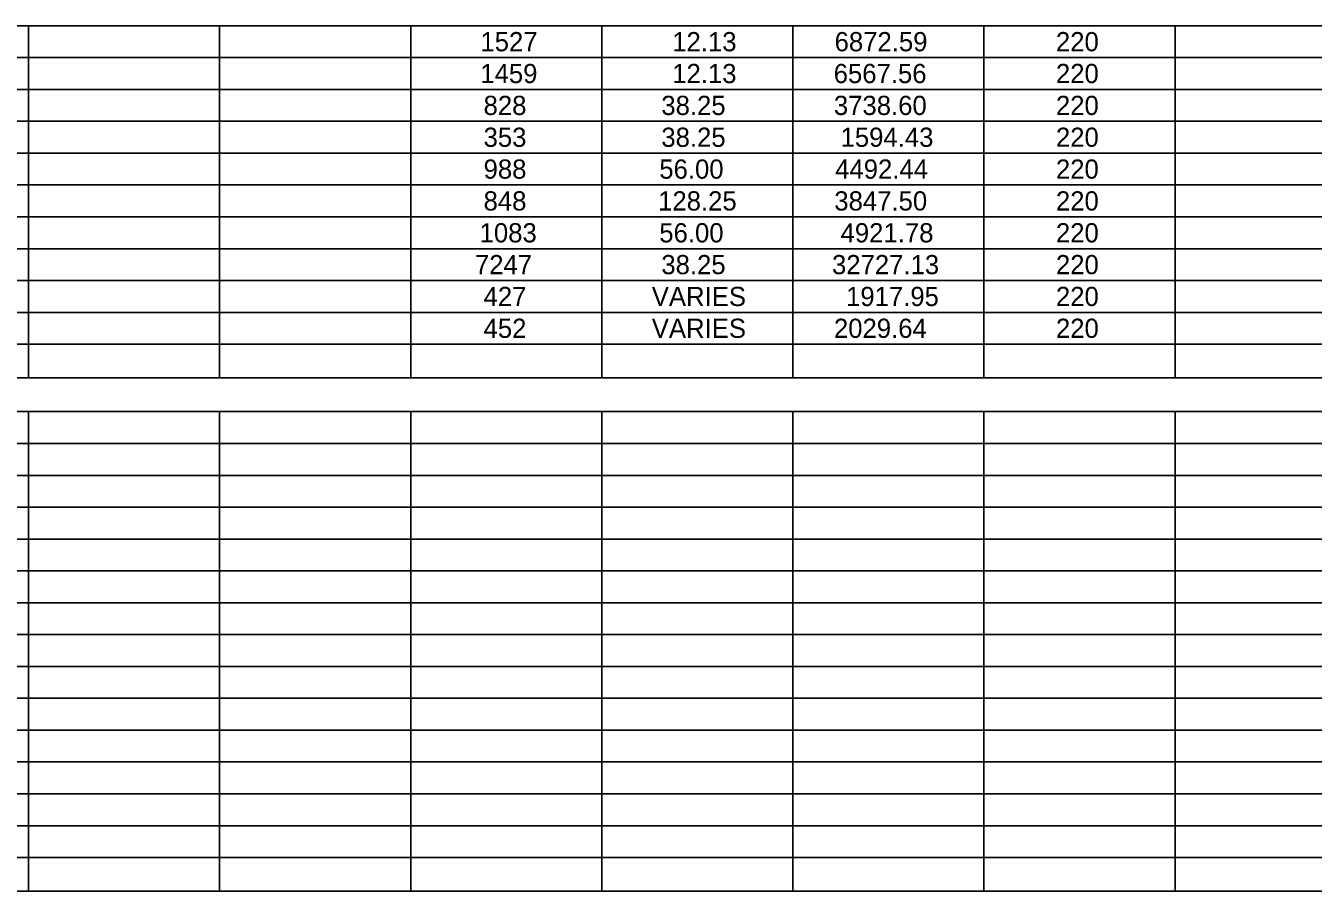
# Model space of a CAD drawing. Extents: x 1226590 to 1228573, y 151304 to 154224.
# Drawn here: x 1227484.8 to 1227748.5, y 151964.1 to 152141.4 of the extents above; entities that cross this region are included whole.
import ezdxf

# ---------------------------------------------------------------- set-up
doc = ezdxf.new("R2010")
doc.units = 0
doc.layers.add('R_Dimension', color=7, linetype='Continuous')

msp = doc.modelspace()

# ---------------------------------------------------------------- linework, layer by layer
at = {"layer": 'R_Dimension'}
for p, q in [((1226590.27, 152141.36), (1228150.73, 152141.36)), ((1227485.41, 152069.23), (1227485.41, 152141.36)), ((1227524.55, 152069.23), (1227524.55, 152141.36)), ((1227563.69, 152069.23), (1227563.69, 152141.36)), ((1227602.82, 152069.23), (1227602.82, 152141.36)), ((1227641.96, 152069.23), (1227641.96, 152141.36)), ((1227681.09, 152069.23), (1227681.09, 152141.36)), ((1227720.23, 152069.23), (1227720.23, 152141.36)), ((1226590.27, 152134.84), (1228150.73, 152134.84)), ((1226590.27, 152128.31), (1228150.73, 152128.31)), ((1226590.27, 152121.79), (1228150.73, 152121.79)), ((1226590.27, 152115.27), (1228150.73, 152115.27)), ((1226590.27, 152108.75), (1228150.73, 152108.75)), ((1226590.27, 152102.22), (1228150.73, 152102.22)), ((1226590.27, 152095.7), (1228150.73, 152095.7)), ((1226590.27, 152089.18), (1228150.73, 152089.18)), ((1226590.27, 152082.65), (1228150.73, 152082.65)), ((1226590.27, 152076.13), (1228150.73, 152076.13)), ((1226590.27, 152069.23), (1228150.73, 152069.23)), ((1226590.27, 152062.32), (1228150.73, 152062.32)), ((1227485.41, 151964.1), (1227485.41, 152062.32)), ((1227524.55, 151964.1), (1227524.55, 152062.32)), ((1227563.69, 151964.1), (1227563.69, 152062.32)), ((1227602.82, 151964.1), (1227602.82, 152062.32)), ((1227641.96, 151964.1), (1227641.96, 152062.32)), ((1227681.09, 151964.1), (1227681.09, 152062.32)), ((1227720.23, 151964.1), (1227720.23, 152062.32)), ((1226590.27, 152055.8), (1228150.73, 152055.8)), ((1226590.27, 152049.27), (1228150.73, 152049.27)), ((1226590.27, 152042.75), (1228150.73, 152042.75)), ((1226590.27, 152036.23), (1228150.73, 152036.23)), ((1226590.27, 152029.71), (1228150.73, 152029.71)), ((1226590.27, 152023.18), (1228150.73, 152023.18)), ((1226590.27, 152016.66), (1228150.73, 152016.66)), ((1226590.27, 152010.14), (1228150.73, 152010.14)), ((1226590.27, 152003.61), (1228150.73, 152003.61)), ((1226590.27, 151997.09), (1228150.73, 151997.09)), ((1226590.27, 151990.57), (1228150.73, 151990.57)), ((1226590.27, 151984.05), (1228150.73, 151984.05)), ((1226590.27, 151977.52), (1228150.73, 151977.52)), ((1226590.27, 151971), (1228150.73, 151971)), ((1226590.27, 151964.1), (1228150.73, 151964.1))]:
    msp.add_line(p, q, dxfattribs=at)

# ---------------------------------------------------------------- texts
for s, p in [('1527', (1227577.96, 152136.13)), ('12.13', (1227617.25, 152136.13)), ('6872.59', (1227650.51, 152136.13)), ('220', (1227695.84, 152136.13)), ('1459', (1227577.94, 152129.61)), ('12.13', (1227617.25, 152129.61)), ('6567.56', (1227650.32, 152129.61)), ('220', (1227695.84, 152129.61)), ('828', (1227578.61, 152123.08)), ('38.25', (1227615.02, 152123.08)), ('3738.60', (1227650.36, 152123.08)), ('220', (1227695.84, 152123.08)), ('353', (1227578.61, 152116.56)), ('38.25', (1227615.02, 152116.56)), ('1594.43', (1227651.73, 152116.56)), ('220', (1227695.84, 152116.56)), ('988', (1227578.61, 152110.04)), ('56.00', (1227614.6, 152110.04)), ('4492.44', (1227650.62, 152110.04)), ('220', (1227695.84, 152110.04)), ('848', (1227578.61, 152103.52)), ('128.25', (1227614.36, 152103.52)), ('3847.50', (1227650.45, 152103.52)), ('220', (1227695.84, 152103.52)), ('1083', (1227577.8, 152096.99)), ('56.00', (1227614.6, 152096.99)), ('4921.78', (1227651.73, 152096.99)), ('220', (1227695.84, 152096.99)), ('7247', (1227576.84, 152090.47)), ('38.25', (1227615.02, 152090.47)), ('32727.13', (1227649.97, 152090.47)), ('220', (1227695.84, 152090.47)), ('427', (1227578.61, 152083.95)), ('VARIES', (1227613.06, 152083.95)), ('1917.95', (1227652.85, 152083.95)), ('220', (1227695.84, 152083.95)), ('452', (1227578.61, 152077.43)), ('VARIES', (1227613.06, 152077.43)), ('2029.64', (1227650.37, 152077.43)), ('220', (1227695.84, 152077.43))]:
    msp.add_text(s, height=3.935, dxfattribs=at).set_placement(p)

doc.saveas('drawing.dxf')
